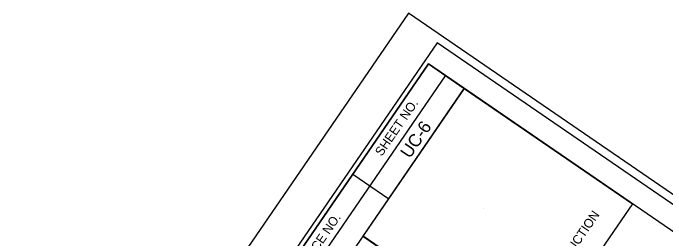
# Model space of a CAD drawing. Extents: x 1439200 to 1641636, y 393269 to 606444.
# Drawn here: x 1641185.6 to 1641330.1, y 394022.9 to 394072.9 of the extents above; entities that cross this region are included whole.
import ezdxf

# ---------------------------------------------------------------- set-up
doc = ezdxf.new("R2010")
doc.units = 0
for name, color, linetype in [('Sheet Data Field CELL', 7, 'Continuous'), ('Sheet Plot Border Inside CELL', 7, 'Continuous'), ('Sheet Plot Border Outside CELL', 7, 'Continuous'), ('UC Plan Sheet 34 CELL', 7, 'Continuous')]:
    doc.layers.add(name, color=color, linetype=linetype)

msp = doc.modelspace()

# ---------------------------------------------------------------- linework, layer by layer
at = {"layer": 'Sheet Plot Border Inside CELL'}
msp.add_lwpolyline([(1641279.54, 394066.32), (1640902.54, 393516.56), (1641250.61, 393277.88), (1641627.6, 393827.64)], close=True, dxfattribs=at)
at = {"layer": 'Sheet Plot Border Outside CELL'}
msp.add_lwpolyline([(1641273.15, 394072.88), (1640892.2, 393517.35), (1641255.07, 393268.51), (1641636.02, 393824.04)], close=True, dxfattribs=at)
at = {"layer": 'UC Plan Sheet 34 CELL'}
for p, q in [((1641236.17, 393993.07), (1641281.38, 394059)), ((1641275.08, 394045.39), (1641275.08, 394045.39)), ((1641260.83, 394037.23), (1641268.78, 394031.77)), ((1641289.82, 394029.55), (1641289.82, 394029.55))]:
    msp.add_line(p, q, dxfattribs=at)
msp.add_lwpolyline([(1641277.55, 394061.62), (1640938.22, 393566.79), (1641284.6, 393329.26), (1641623.93, 393824.09)], close=True, dxfattribs=at)
for points in [[(1641232.34, 393995.7), (1641277.55, 394061.62), (1641285.49, 394056.17)], [(1641285.49, 394056.17), (1641240.28, 393990.25), (1641232.34, 393995.7)], [(1641322.71, 394030.65), (1641300.29, 393997.96), (1641263.09, 394023.47), (1641285.51, 394056.16)], [(1641285.51, 394056.16), (1641322.71, 394030.65)], [(1641263.07, 394023.48), (1641300.29, 393997.96), (1641277.5, 393964.73), (1641232.34, 393995.7)]]:
    msp.add_lwpolyline(points, dxfattribs=at)

# ---------------------------------------------------------------- texts
at = {"layer": 'Sheet Data Field CELL'}
msp.add_text('UC-6', height=2.8, rotation=55.5597, dxfattribs=at).set_placement((1641273.45, 394040.53))
at = {"layer": 'UC Plan Sheet 34 CELL'}
for s, height, p in [('SHEET NO.', 2.005, (1641267.25, 394041.06)), ('UTILITY CONSTRUCTION', 2.0046, (1641297.28, 394001.61)), ('PROJECT REFERENCE NO.', 2.0046, (1641238.33, 393998.57))]:
    msp.add_text(s, height=height, rotation=55.5597, dxfattribs=at).set_placement(p)

doc.saveas('drawing.dxf')
